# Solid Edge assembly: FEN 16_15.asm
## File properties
Title: Zylinder
Author: bmolnar
Template: iso assembly.asm
Last saved by: bmolnar
Revision: 15
Application: Solid Edge
Username: bmolnar
Dokumentum tartalom típus: 1
Document Number: FEN 16/15
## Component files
Kit_2.par
Profilrohr.par
Kolbenstange.par
Kit_1.par
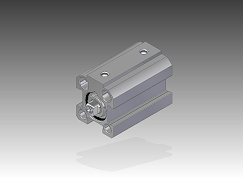
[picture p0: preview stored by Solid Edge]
